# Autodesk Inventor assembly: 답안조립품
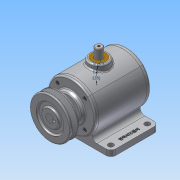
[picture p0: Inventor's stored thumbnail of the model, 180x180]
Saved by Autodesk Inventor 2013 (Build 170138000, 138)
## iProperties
Created: 2015-08
Part Number: 답안조립품
Document SubType Name: Assembly
Designer: Administrator
Mass: 2990.33 g
Surface Area: 2017.36 cm^2
Volume: 938.374 cm^3
Density: 3.18671 g/cm^3
Author: Administrator
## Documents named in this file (14)
- C:\Users\Administrator\Desktop\350806V1026\답안조립품.iam
- C:\Users\Administrator\Desktop\350806V1026\본체.ipt
- C:\Users\Administrator\Desktop\350806V1026\앞커버.ipt
- C:\Users\Administrator\Desktop\350806V1026\M4-소켓머리.ipt
- C:\Users\Administrator\Desktop\350806V1026\오일실.ipt
- C:\Users\Administrator\Desktop\350806V1026\베어링 6203.ipt
- C:\Users\Administrator\Desktop\350806V1026\뒷커버.ipt
- C:\Users\Administrator\Desktop\350806V1026\부시.ipt
- C:\Users\Administrator\Desktop\350806V1026\축.ipt
- C:\Users\Administrator\Desktop\350806V1026\KS B 1311 - 5 x 5 x 18I.ipt
- C:\Users\Administrator\Desktop\350806V1026\V-벨트풀리.ipt
- C:\Users\Administrator\Desktop\350806V1026\KS B 1028  - 납작점M4x5.ipt
- C:\Users\Administrator\Desktop\350806V1026\슬라이더.ipt
- C:\Users\Administrator\Desktop\350806V1026\13-스프링.ipt
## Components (15 placed, 7 different names)
1. 8-오일실:1
2. 7-베어링 6203:1
3. 7-베어링 6203:2
4. KS B 1311 (I) 5 x 5 x 18:1 — 각도:1, 각도:2
5. V-벨트풀리:1 — 각도:2, 플러쉬:1
6. KS B 1028 납작점 - 미터 납작점M4x5:1
7. 13-스프링:1
8. 9-M4-소켓머리:1
9. 9-M4-소켓머리:2
10. 9-M4-소켓머리:3
11. 9-M4-소켓머리:4
12. 9-M4-소켓머리:5
13. 9-M4-소켓머리:6
14. 9-M4-소켓머리:7
15. 9-M4-소켓머리:8
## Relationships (3: Angle 2, Flush 1)
- 각도:1 [Angle]: KS B 1311 (I) 5 x 5 x 18:1
- 각도:2 [Angle]: KS B 1311 (I) 5 x 5 x 18:1 ↔ V-벨트풀리:1
- 플러쉬:1 [Flush]: V-벨트풀리:1
